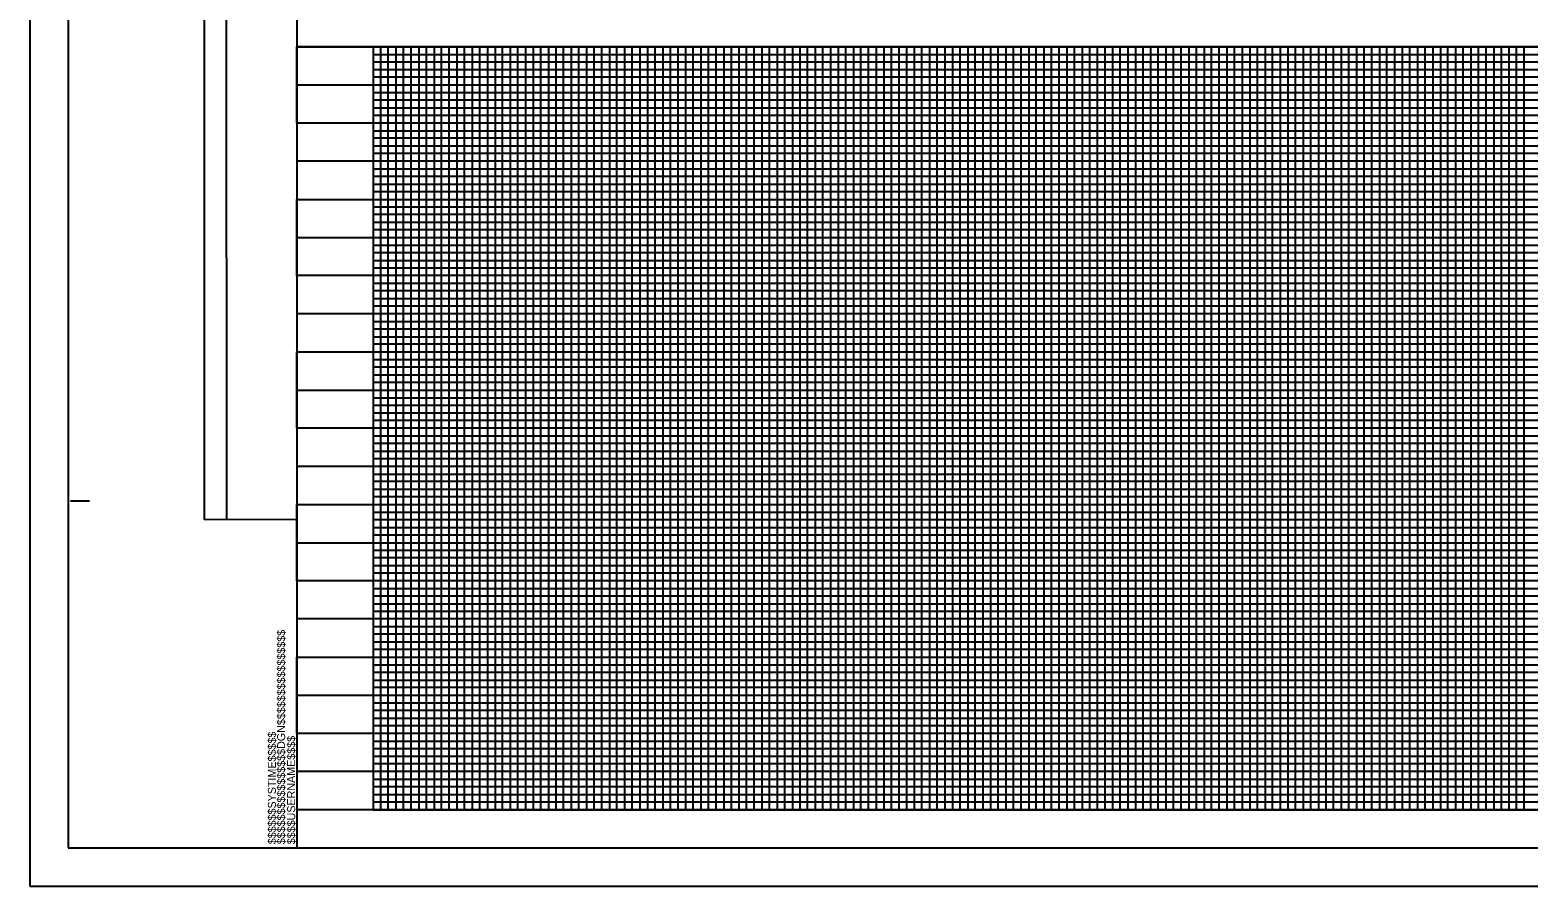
# Model space of a CAD drawing. Extents: x 1852853 to 1854818, y 258638 to 259738.
# Drawn here: x 1852853 to 1853836, y 258638 to 259199 of the extents above; entities that cross this region are included whole.
import ezdxf

# ---------------------------------------------------------------- set-up
doc = ezdxf.new("R2010")
doc.units = 0
for name, color, linetype in [('Old_Level_41', 7, 'Continuous'), ('Old_Level_42', 7, 'Continuous'), ('Old_Level_62', 7, 'Continuous'), ('Old_Level_63', 7, 'Continuous'), ('Scratch_Level_3', 7, 'Continuous'), ('Sheet Block Revision CELL', 7, 'Continuous'), ('Sheet Profile CELL', 7, 'Continuous'), ('Sheet Profile Grid Major CELL', 7, 'Continuous'), ('Sheet Profile Grid Middle CELL', 7, 'Continuous'), ('Sheet Profile Grid Minor CELL', 7, 'Continuous')]:
    doc.layers.add(name, color=color, linetype=linetype)

msp = doc.modelspace()

# ---------------------------------------------------------------- linework, layer by layer
at = {"layer": 'Old_Level_41'}
msp.add_line((1852879.58, 258890.99), (1852892.08, 258890.99), dxfattribs=at)
at = {"layer": 'Old_Level_42'}
msp.add_line((1853028.08, 258688.49), (1853028.08, 258688.49), dxfattribs=at)
at = {"layer": 'Old_Level_62'}
msp.add_lwpolyline([(1852878.08, 258663.49), (1854528.08, 258663.49), (1854528.08, 259713.49), (1852878.08, 259713.49)], close=True, dxfattribs=at)
at = {"layer": 'Old_Level_63'}
msp.add_lwpolyline([(1852853.08, 258638.49), (1854553.08, 258638.49), (1854553.08, 259738.49), (1852853.08, 259738.49)], close=True, dxfattribs=at)
at = {"layer": 'Scratch_Level_3'}
msp.add_lwpolyline([(1853078.08, 259188.49), (1853078.08, 258688.49), (1854478.08, 258688.49), (1854478.08, 259188.49)], close=True, dxfattribs=at)
at = {"layer": 'Sheet Block Revision CELL'}
msp.add_line((1852982.09, 258878.59), (1852982.08, 259669.23), dxfattribs=at)
msp.add_lwpolyline([(1852967.54, 258878.57), (1852967.54, 259669.22), (1853028.08, 259669.24), (1853028.08, 258878.59)], close=True, dxfattribs=at)
at = {"layer": 'Sheet Profile CELL'}
for p, q in [((1854528.08, 259188.49), (1853028.08, 259188.49)), ((1854528.08, 258688.49), (1853028.08, 258688.49))]:
    msp.add_line(p, q, dxfattribs=at)
msp.add_lwpolyline([(1854528.08, 259713.49), (1853028.08, 259713.49), (1853028.08, 258663.49), (1854528.08, 258663.49)], close=True, dxfattribs=at)
msp.add_lwpolyline([(1853065.58, 258663.49), (1853065.58, 258663.49)], dxfattribs=at)
at = {"layer": 'Sheet Profile Grid Major CELL'}
for points in [[(1854528.08, 259138.49), (1853028.08, 259138.49), (1853028.08, 259188.49), (1854528.08, 259188.49)], [(1853078.08, 259188.49), (1853078.08, 258688.49), (1853128.08, 258688.49), (1853128.08, 259188.49)], [(1853178.08, 259188.49), (1853178.08, 258688.49), (1853228.08, 258688.49), (1853228.08, 259188.49)], [(1853278.08, 259188.49), (1853278.08, 258688.49), (1853328.08, 258688.49), (1853328.08, 259188.49)], [(1853378.08, 259188.49), (1853378.08, 258688.49), (1853428.08, 258688.49), (1853428.08, 259188.49)], [(1853478.08, 259188.49), (1853478.08, 258688.49), (1853528.08, 258688.49), (1853528.08, 259188.49)], [(1853578.08, 259188.49), (1853578.08, 258688.49), (1853628.08, 258688.49), (1853628.08, 259188.49)], [(1853678.08, 259188.49), (1853678.08, 258688.49), (1853728.08, 258688.49), (1853728.08, 259188.49)], [(1853778.08, 259188.49), (1853778.08, 258688.49), (1853828.08, 258688.49), (1853828.08, 259188.49)], [(1854528.08, 259038.49), (1853028.08, 259038.49), (1853028.08, 259088.49), (1854528.08, 259088.49)], [(1854528.08, 258938.49), (1853028.08, 258938.49), (1853028.08, 258988.49), (1854528.08, 258988.49)], [(1854528.08, 258838.49), (1853028.08, 258838.49), (1853028.08, 258888.49), (1854528.08, 258888.49)], [(1854528.08, 258738.49), (1853028.08, 258738.49), (1853028.08, 258788.49), (1854528.08, 258788.49)]]:
    msp.add_lwpolyline(points, dxfattribs=at)
at = {"layer": 'Sheet Profile Grid Middle CELL'}
for points in [[(1853028.08, 259188.49), (1853028.08, 259163.49), (1854528.08, 259163.49)], [(1853103.08, 258688.49), (1853103.08, 259188.49)], [(1853153.08, 259188.49), (1853153.08, 258688.49), (1853203.08, 258688.49), (1853203.08, 259188.49)], [(1853253.08, 259188.49), (1853253.08, 258688.49), (1853303.08, 258688.49), (1853303.08, 259188.49)], [(1853353.08, 259188.49), (1853353.08, 258688.49), (1853403.08, 258688.49), (1853403.08, 259188.49)], [(1853453.08, 259188.49), (1853453.08, 258688.49), (1853503.08, 258688.49), (1853503.08, 259188.49)], [(1853553.08, 259188.49), (1853553.08, 258688.49), (1853603.08, 258688.49), (1853603.08, 259188.49)], [(1853653.08, 259188.49), (1853653.08, 258688.49), (1853703.08, 258688.49), (1853703.08, 259188.49)], [(1853753.08, 259188.49), (1853753.08, 258688.49), (1853803.08, 258688.49), (1853803.08, 259188.49)], [(1854528.08, 259113.49), (1853028.08, 259113.49), (1853028.08, 259063.49), (1854528.08, 259063.49)], [(1854528.08, 259013.49), (1853028.08, 259013.49), (1853028.08, 258963.49), (1854528.08, 258963.49)], [(1854528.08, 258913.49), (1853028.08, 258913.49), (1853028.08, 258863.49), (1854528.08, 258863.49)], [(1854528.08, 258813.49), (1853028.08, 258813.49), (1853028.08, 258763.49), (1854528.08, 258763.49)], [(1854528.08, 258713.49), (1853028.08, 258713.49)]]:
    msp.add_lwpolyline(points, dxfattribs=at)
at = {"layer": 'Sheet Profile Grid Minor CELL'}
for points in [[(1853083.08, 259188.49), (1853083.08, 258688.49), (1853088.08, 258688.49), (1853088.08, 259188.49)], [(1853093.08, 259188.49), (1853093.08, 258688.49), (1853098.08, 258688.49), (1853098.08, 259188.49)], [(1853108.08, 259188.49), (1853108.08, 258688.49), (1853113.08, 258688.49), (1853113.08, 259188.49)], [(1853118.08, 259188.49), (1853118.08, 258688.49), (1853123.08, 258688.49), (1853123.08, 259188.49)], [(1853133.08, 259188.49), (1853133.08, 258688.49), (1853138.08, 258688.49), (1853138.08, 259188.49)], [(1853143.08, 259188.49), (1853143.08, 258688.49), (1853148.08, 258688.49), (1853148.08, 259188.49)], [(1853158.08, 259188.49), (1853158.08, 258688.49), (1853163.08, 258688.49), (1853163.08, 259188.49)], [(1853168.08, 259188.49), (1853168.08, 258688.49), (1853173.08, 258688.49), (1853173.08, 259188.49)], [(1853183.08, 259188.49), (1853183.08, 258688.49), (1853188.08, 258688.49), (1853188.08, 259188.49)], [(1853193.08, 259188.49), (1853193.08, 258688.49), (1853198.08, 258688.49), (1853198.08, 259188.49)], [(1853208.08, 259188.49), (1853208.08, 258688.49), (1853213.08, 258688.49), (1853213.08, 259188.49)], [(1853218.08, 259188.49), (1853218.08, 258688.49), (1853223.08, 258688.49), (1853223.08, 259188.49)], [(1853233.08, 259188.49), (1853233.08, 258688.49), (1853238.08, 258688.49), (1853238.08, 259188.49)], [(1853243.08, 258688.49), (1853248.08, 258688.49), (1853248.08, 259188.49)], [(1853243.08, 259188.49), (1853243.08, 258688.49)], [(1853258.08, 259188.49), (1853258.08, 258688.49), (1853263.08, 258688.49), (1853263.08, 259188.49)], [(1853268.08, 259188.49), (1853268.08, 258688.49), (1853273.08, 258688.49), (1853273.08, 259188.49)], [(1853283.08, 259188.49), (1853283.08, 258688.49), (1853288.08, 258688.49), (1853288.08, 259188.49)], [(1853293.08, 259188.49), (1853293.08, 258688.49), (1853298.08, 258688.49), (1853298.08, 259188.49)], [(1853308.08, 259188.49), (1853308.08, 258688.49), (1853313.08, 258688.49), (1853313.08, 259188.49)], [(1853318.08, 259188.49), (1853318.08, 258688.49), (1853323.08, 258688.49), (1853323.08, 259188.49)], [(1853333.08, 259188.49), (1853333.08, 258688.49), (1853338.08, 258688.49), (1853338.08, 259188.49)], [(1853343.08, 259188.49), (1853343.08, 258688.49), (1853348.08, 258688.49), (1853348.08, 259188.49)], [(1853358.08, 259188.49), (1853358.08, 258688.49), (1853363.08, 258688.49), (1853363.08, 259188.49)], [(1853368.08, 259188.49), (1853368.08, 258688.49), (1853373.08, 258688.49), (1853373.08, 259188.49)], [(1853383.08, 259188.49), (1853383.08, 258688.49), (1853388.08, 258688.49), (1853388.08, 259188.49)], [(1853393.08, 259188.49), (1853393.08, 258688.49), (1853398.08, 258688.49), (1853398.08, 259188.49)], [(1853408.08, 259188.49), (1853408.08, 258688.49), (1853423.08, 258688.49), (1853423.08, 259188.49)], [(1853413.08, 259188.49), (1853413.08, 258688.49), (1853418.08, 258688.49), (1853418.08, 259188.49)], [(1853413.08, 259188.49), (1853413.08, 258688.49), (1853418.08, 258688.49), (1853418.08, 259188.49)], [(1853433.08, 259188.49), (1853433.08, 258688.49), (1853438.08, 258688.49), (1853438.08, 259188.49)], [(1853443.08, 259188.49), (1853443.08, 258688.49), (1853448.08, 258688.49), (1853448.08, 259188.49)], [(1853458.08, 259188.49), (1853458.08, 258688.49), (1853463.08, 258688.49), (1853463.08, 259188.49)], [(1853468.08, 259188.49), (1853468.08, 258688.49), (1853473.08, 258688.49), (1853473.08, 259188.49)], [(1853483.08, 259188.49), (1853483.08, 258688.49), (1853488.08, 258688.49), (1853488.08, 259188.49)], [(1853493.08, 259188.49), (1853493.08, 258688.49), (1853498.08, 258688.49), (1853498.08, 259188.49)], [(1853508.08, 259188.49), (1853508.08, 258688.49), (1853513.08, 258688.49), (1853513.08, 259188.49)], [(1853518.08, 259188.49), (1853518.08, 258688.49), (1853523.08, 258688.49), (1853523.08, 259188.49)], [(1853533.08, 259188.49), (1853533.08, 258688.49), (1853538.08, 258688.49), (1853538.08, 259188.49)], [(1853543.08, 259188.49), (1853543.08, 258688.49), (1853548.08, 258688.49), (1853548.08, 259188.49)], [(1853558.08, 259188.49), (1853558.08, 258688.49)], [(1853563.08, 259188.49), (1853563.08, 258688.49), (1853568.08, 258688.49), (1853568.08, 259188.49)], [(1853573.08, 259188.49), (1853573.08, 258688.49), (1853583.08, 258688.49), (1853583.08, 259188.49)], [(1853588.08, 259188.49), (1853588.08, 258688.49), (1853593.08, 258688.49), (1853593.08, 259188.49)], [(1853598.08, 259188.49), (1853598.08, 258688.49)], [(1853608.08, 258688.49), (1853608.08, 259188.49)], [(1853613.08, 259188.49), (1853613.08, 258688.49), (1853618.08, 258688.49), (1853618.08, 259188.49)], [(1853623.08, 259188.49), (1853623.08, 258688.49), (1853633.08, 258688.49), (1853633.08, 259188.49)], [(1853638.08, 259188.49), (1853638.08, 258688.49), (1853638.08, 258688.49), (1853643.08, 258688.49), (1853643.08, 259188.49)], [(1853648.08, 259188.49), (1853648.08, 258688.49), (1853658.08, 258688.49), (1853658.08, 259188.49)], [(1853663.08, 259188.49), (1853663.08, 258688.49), (1853668.08, 258688.49), (1853668.08, 259188.49)], [(1853673.08, 259188.49), (1853673.08, 258688.49), (1853683.08, 258688.49), (1853683.08, 259188.49)], [(1853688.08, 259188.49), (1853688.08, 258688.49), (1853693.08, 258688.49), (1853693.08, 259188.49)], [(1853698.08, 259188.49), (1853698.08, 258688.49), (1853708.08, 258688.49), (1853708.08, 259188.49)], [(1853713.08, 259188.49), (1853713.08, 258688.49), (1853718.08, 258688.49), (1853718.08, 259188.49)], [(1853723.08, 259188.49), (1853723.08, 258688.49), (1853733.08, 258688.49), (1853733.08, 259188.49)], [(1853738.08, 259188.49), (1853738.08, 258688.49), (1853743.08, 258688.49), (1853743.08, 259188.49)], [(1853748.08, 259188.49), (1853748.08, 258688.49), (1853758.08, 258688.49), (1853758.08, 259188.49)], [(1853763.08, 259188.49), (1853763.08, 258688.49), (1853768.08, 258688.49), (1853768.08, 259188.49)], [(1853773.08, 259188.49), (1853773.08, 258688.49), (1853783.08, 258688.49), (1853783.08, 259188.49)], [(1853788.08, 259188.49), (1853788.08, 258688.49)], [(1853788.08, 258688.49), (1853793.08, 258688.49), (1853793.08, 259188.49)], [(1853798.08, 259188.49), (1853798.08, 258688.49), (1853808.08, 258688.49), (1853808.08, 259188.49)], [(1853813.08, 259188.49), (1853813.08, 258688.49), (1853818.08, 258688.49), (1853818.08, 259188.49)], [(1853823.08, 259188.49), (1853823.08, 258688.49), (1853833.08, 258688.49), (1853833.08, 259188.49)], [(1853078.08, 259183.49), (1854478.08, 259183.49)], [(1854478.08, 259178.49), (1853078.08, 259178.49), (1853078.08, 259173.49), (1854478.08, 259173.49)], [(1854478.08, 259168.49), (1853078.08, 259168.49), (1853078.08, 259158.49), (1854478.08, 259158.49)], [(1854478.08, 259153.49), (1853078.08, 259153.49), (1853078.08, 259148.49), (1854478.08, 259148.49)], [(1854478.08, 259143.49), (1853078.08, 259143.49), (1853078.08, 259133.49), (1854478.08, 259133.49)], [(1854478.08, 259128.49), (1853078.08, 259128.49), (1853078.08, 259123.49), (1854478.08, 259123.49)], [(1854478.08, 259118.49), (1853078.08, 259118.49), (1853078.08, 259108.49), (1854478.08, 259108.49)], [(1854478.08, 259103.49), (1853078.08, 259103.49), (1853078.08, 259098.49), (1854478.08, 259098.49)], [(1854478.08, 259093.49), (1853078.08, 259093.49), (1853078.08, 259083.49), (1854478.08, 259083.49)], [(1854478.08, 259078.49), (1853078.08, 259078.49), (1853078.08, 259073.49), (1854478.08, 259073.49)], [(1854478.08, 259068.49), (1853078.08, 259068.49), (1853078.08, 259058.49), (1854478.08, 259058.49)], [(1854478.08, 259053.49), (1853078.08, 259053.49), (1853078.08, 259048.49), (1854478.08, 259048.49)], [(1854478.08, 259043.49), (1853078.08, 259043.49), (1853078.08, 259033.49), (1854478.08, 259033.49)], [(1854478.08, 259028.49), (1853078.08, 259028.49), (1853078.08, 259023.49), (1854478.08, 259023.49)], [(1854478.08, 259018.49), (1853078.08, 259018.49), (1853078.08, 259008.49), (1854478.08, 259008.49)], [(1854478.08, 259003.49), (1853078.08, 259003.49), (1853078.08, 258998.49), (1854478.08, 258998.49)], [(1854478.08, 258993.49), (1853078.08, 258993.49), (1853078.08, 258983.49), (1854478.08, 258983.49)], [(1854478.08, 258978.49), (1853078.08, 258978.49), (1853078.08, 258973.49), (1854478.08, 258973.49)], [(1854478.08, 258968.49), (1853078.08, 258968.49), (1853078.08, 258958.49), (1854478.08, 258958.49)], [(1854478.08, 258953.49), (1853078.08, 258953.49), (1853078.08, 258948.49), (1854478.08, 258948.49)], [(1854478.08, 258943.49), (1853078.08, 258943.49), (1853078.08, 258933.49), (1854478.08, 258933.49)], [(1854478.08, 258928.49), (1853078.08, 258928.49), (1853078.08, 258923.49), (1854478.08, 258923.49)], [(1854478.08, 258918.49), (1853078.08, 258918.49), (1853078.08, 258908.49), (1854478.08, 258908.49)], [(1854478.08, 258903.49), (1853078.08, 258903.49), (1853078.08, 258898.49), (1854478.08, 258898.49)], [(1854478.08, 258893.49), (1853078.08, 258893.49)], [(1853078.08, 258883.49), (1854478.08, 258883.49)], [(1854478.08, 258878.49), (1853078.08, 258878.49), (1853078.08, 258873.49), (1854478.08, 258873.49)], [(1854478.08, 258868.49), (1853078.08, 258868.49)], [(1853078.08, 258858.49), (1854478.08, 258858.49)], [(1854478.08, 258853.49), (1853078.08, 258853.49), (1853078.08, 258848.49), (1854478.08, 258848.49)], [(1854478.08, 258843.49), (1853078.08, 258843.49), (1853078.08, 258833.49), (1854478.08, 258833.49)], [(1854478.08, 258828.49), (1853078.08, 258828.49), (1853078.08, 258823.49), (1854478.08, 258823.49)], [(1854478.08, 258818.49), (1853078.08, 258818.49), (1853078.08, 258808.49), (1854478.08, 258808.49)], [(1854478.08, 258803.49), (1853078.08, 258803.49), (1853078.08, 258798.49), (1854478.08, 258798.49)], [(1854478.08, 258793.49), (1853078.08, 258793.49), (1853078.08, 258783.49), (1854478.08, 258783.49)], [(1854478.08, 258778.49), (1853078.08, 258778.49), (1853078.08, 258773.49), (1854478.08, 258773.49)], [(1854478.08, 258768.49), (1853078.08, 258768.49), (1853078.08, 258758.49), (1854478.08, 258758.49)], [(1854478.08, 258753.49), (1853078.08, 258753.49), (1853078.08, 258748.49), (1854478.08, 258748.49)], [(1854478.08, 258743.49), (1853078.08, 258743.49), (1853078.08, 258733.49), (1854478.08, 258733.49)], [(1854478.08, 258728.49), (1853078.08, 258728.49), (1853078.08, 258723.49), (1854478.08, 258723.49)], [(1854478.08, 258718.49), (1853078.08, 258718.49), (1853078.08, 258708.49), (1854478.08, 258708.49)], [(1854478.08, 258703.49), (1853078.08, 258703.49), (1853078.08, 258698.49), (1854478.08, 258698.49)], [(1854478.08, 258693.49), (1853078.08, 258693.49), (1853078.08, 258688.49), (1854478.08, 258688.49)]]:
    msp.add_lwpolyline(points, dxfattribs=at)

# ---------------------------------------------------------------- texts
at = {"layer": 'Sheet Profile CELL'}
for s, p in [('$$$$$$$$$$$$$$$$DGN$$$$$$$$$$$$$$$$', (1853020.43, 258665.86)), ('$$$$$$SYSTIME$$$$$', (1853014.38, 258665.86)), ('$$$$USERNAME$$$$', (1853027, 258665.87))]:
    msp.add_text(s, height=5.25, rotation=90, dxfattribs=at).set_placement(p)

doc.saveas('drawing.dxf')
